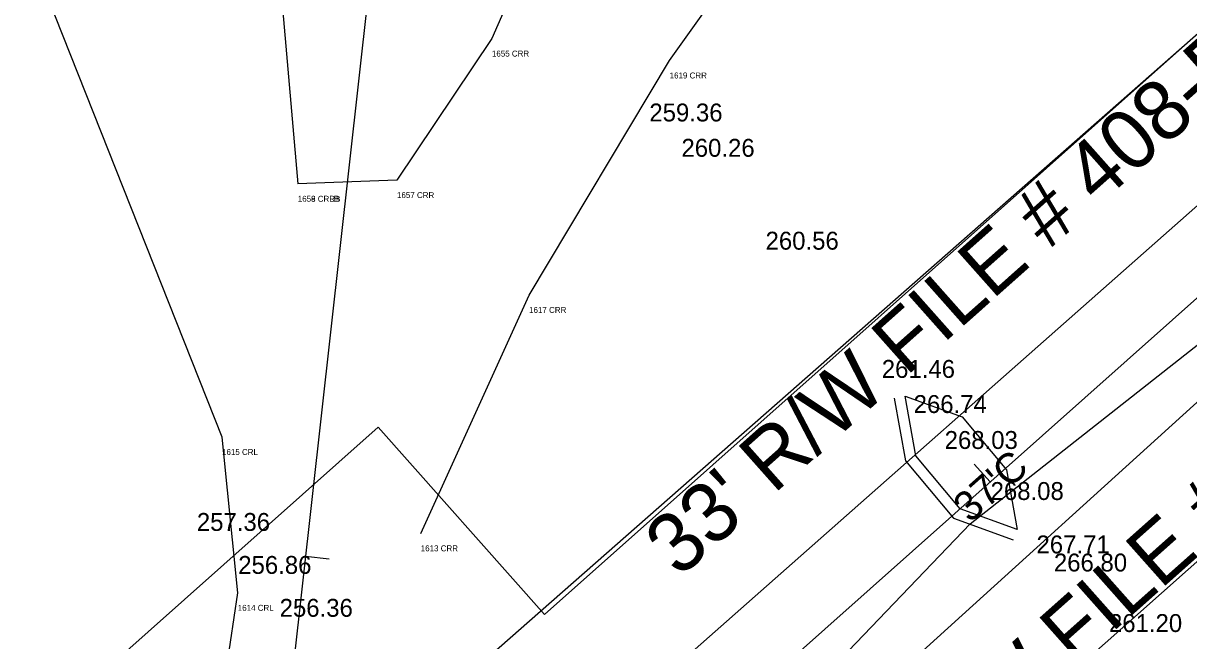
# Model space of a CAD drawing. Extents: x 49683 to 58852, y 49525 to 54803.
# Drawn here: x 55297.8 to 55493.1, y 53247.8 to 53351.3 of the extents above; entities that cross this region are included whole.
import ezdxf

# ---------------------------------------------------------------- set-up
doc = ezdxf.new("R2010")
doc.units = 0
for name, color, linetype in [('Level 1', 7, 'Continuous'), ('Level 10', 7, 'Continuous'), ('Level 11', 7, 'Continuous'), ('Level 13', 7, 'Continuous'), ('Level 18', 7, 'Continuous'), ('Level 20', 7, 'Continuous'), ('Level 25', 7, 'Continuous'), ('Level 3', 7, 'Continuous'), ('Level 32', 7, 'Continuous'), ('Level 34', 7, 'Continuous'), ('Level 48', 7, 'Continuous'), ('Level 60', 7, 'Continuous')]:
    doc.layers.add(name, color=color, linetype=linetype)

msp = doc.modelspace()

# ---------------------------------------------------------------- linework, layer by layer
at = {"layer": 'Level 1'}
for p, q in [((55378.38, 53560.11), (55334.01, 53162.57)), ((52544.81, 50683.3), (55534.58, 53340.86)), ((55459.84, 53274.43), (55457.19, 53277.42)), ((55345.1, 53261.96), (55349.08, 53261.52))]:
    msp.add_line(p, q, dxfattribs=at)
at = {"layer": 'Level 10'}
for p, q in [((55400.08, 53403.15), (55376.34, 53348.69)), ((55406.13, 53345.02), (55429.23, 53377.48)), ((55331.1, 53281.94), (55300.16, 53360.05)), ((55341.18, 53354.47), (55343.8, 53324.36)), ((55376.34, 53348.69), (55360.43, 53324.98)), ((55382.57, 53305.74), (55406.13, 53345.02)), ((55360.43, 53324.98), (55343.8, 53324.36)), ((55364.41, 53265.8), (55382.57, 53305.74)), ((55333.74, 53255.83), (55331.1, 53281.94)), ((55326.1, 53204), (55333.74, 53255.83))]:
    msp.add_line(p, q, dxfattribs=at)
at = {"layer": 'Level 11'}
msp.add_line((55359.8, 53231.14), (55681.7, 53513.84), dxfattribs=at)
at = {"layer": 'Level 13'}
for p, q in [((55385.17, 53252.2), (55512.66, 53365.53)), ((55429.01, 53202.87), (55556.51, 53316.2)), ((55207.78, 53150.72), (55357.26, 53283.59)), ((55357.26, 53283.59), (55385.17, 53252.2))]:
    msp.add_line(p, q, dxfattribs=at)
at = {"layer": 'Level 18'}
for p, q in [((55456.49, 53267.43), (55495.87, 53298.38)), ((55421.77, 53231.22), (55456.49, 53267.43))]:
    msp.add_line(p, q, dxfattribs=at)
at = {"layer": 'Level 20'}
msp.add_line((55390.95, 53169.04), (56142.88, 53837.41), dxfattribs=at)
at = {"layer": 'Level 3'}
for p, q in [((55346.63, 53190.09), (55550.6, 53370.24)), ((55389.47, 53192.62), (55564.43, 53351.07))]:
    msp.add_line(p, q, dxfattribs=at)
at = {"layer": 'Level 34'}
for p, q in [((55443.79, 53288.46), (55445.64, 53277.98)), ((55447.4, 53278.8), (55445.63, 53288.78)), ((55445.63, 53288.78), (55455.16, 53285.32)), ((55455.16, 53285.32), (55462.6, 53276.46)), ((55445.64, 53277.98), (55453.72, 53268.35)), ((55454.83, 53269.94), (55447.4, 53278.8)), ((55462.6, 53276.46), (55464.36, 53266.47)), ((55464.36, 53266.47), (55454.83, 53269.94)), ((55453.72, 53268.35), (55463.72, 53264.71))]:
    msp.add_line(p, q, dxfattribs=at)

# ---------------------------------------------------------------- texts
at = {"layer": 'Level 25'}
for p in [(55407.75, 53258.22), (55435.96, 53209.71)]:
    msp.add_text("33' R/W FILE # 408-B", height=10, rotation=41.6333, dxfattribs=at).set_placement(p)
at = {"layer": 'Level 32'}
for s, p in [('259.36', (55402.73, 53334.82)), ('260.26', (55408.11, 53328.9)), ('260.56', (55422.21, 53313.34)), ('261.46', (55441.69, 53291.86)), ('266.74', (55447.03, 53285.97)), ('268.03', (55452.23, 53279.95)), ('268.08', (55459.93, 53271.4)), ('257.36', (55326.88, 53266.22)), ('267.71', (55467.62, 53262.45)), ('256.86', (55333.82, 53259.02)), ('266.80', (55470.54, 53259.42)), ('256.36', (55340.76, 53251.83)), ('261.20', (55479.77, 53249.28))]:
    msp.add_text(s, height=3, dxfattribs=at).set_placement(p)
at = {"layer": 'Level 48'}
msp.add_text("37'C", height=5, rotation=41.6334, dxfattribs=at).set_placement((55456.5, 53267.42))
at = {"layer": 'Level 60'}
for s, p in [('1655 CRR', (55376.34, 53345.69)), ('1619 CRR', (55406.13, 53342.02)), ('1658 CRRB', (55343.8, 53321.36)), ('1659 CRLB', (55343.8, 53321.36)), ('1657 CRR', (55360.43, 53321.98)), ('1617 CRR', (55382.57, 53302.74)), ('1615 CRL', (55331.1, 53278.94)), ('1613 CRR', (55364.41, 53262.8)), ('1614 CRL', (55333.74, 53252.83))]:
    msp.add_text(s, height=1, dxfattribs=at).set_placement(p)

doc.saveas('drawing.dxf')
